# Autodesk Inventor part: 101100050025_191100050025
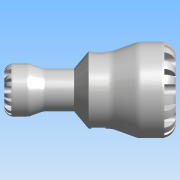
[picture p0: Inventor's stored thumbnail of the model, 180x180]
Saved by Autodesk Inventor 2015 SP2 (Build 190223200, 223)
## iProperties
Created: 2016-12
Part Number: 101100050025_191100050025
Material: PVC-Piping
Description: PLASSON REDUCING COUPLING 50X25 SERIES 1
Document SubType Name: Modeling
Designer: KIM
Mass: 113.204 g
Surface Area: 237.851 cm^2
Volume: 80.8599 cm^3
Density: 1.4 g/cm^3
Appearance: Smooth - White
Author: KIM
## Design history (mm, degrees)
derived "1011.ipt"
feature "Solid1::1011.ipt"
tag "TaggingFeature1"
body "Solid1"
other parameters: "d0" = 151, "d2" = 33.18, "d4" = 85, "d6" = 79, "d7" = 4.16667, "d8" = 47, "d9" = 25, "d10" = 31.25, "d11" = 21.42, "d12" = 51, "d13" = 2.08333, "d14" = 68, "d15" = 37.6, "d16" = 20 deg, "d17" = 20 deg, "d18" = 130 deg, "d26" = 0, "d28" = 360 deg, "d30" = 8 deg, "d31" = 1, "d32" = 8 deg, "d33" = 1, "d35" = 0, "d37" = 360 deg, "d39" = 6.3, "d42" = 6.3, "d43" = 0, "d45" = 360 deg, "d47" = 0.5, "d48" = 8 deg, "d49" = 8 deg, "d50" = 0.5, "d52" = 0, "d54" = 360 deg, "d56" = 9.4, "d57" = 17, "d58" = 0.5, "d60" = 10.2, "d61" = 12.5, "d62" = 16.2, "d63" = 0, "d66" = 0, "d68" = 360 deg, "d75" = 8.49071, "d77" = 66.3, "d78" = 0.85, "d1" = 25, "E_" = 85, "H_" = 151, "l_" = 79, "E1" = 47, "l1" = 51, "Plasson" = 1, "d20" = 7.875, "d21" = 12.5, "d23" = 85, "d40" = 47, "d41" = 31.25, "d59" = 16.98142
